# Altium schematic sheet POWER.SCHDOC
size A4; DrawnBy: *Drawb By
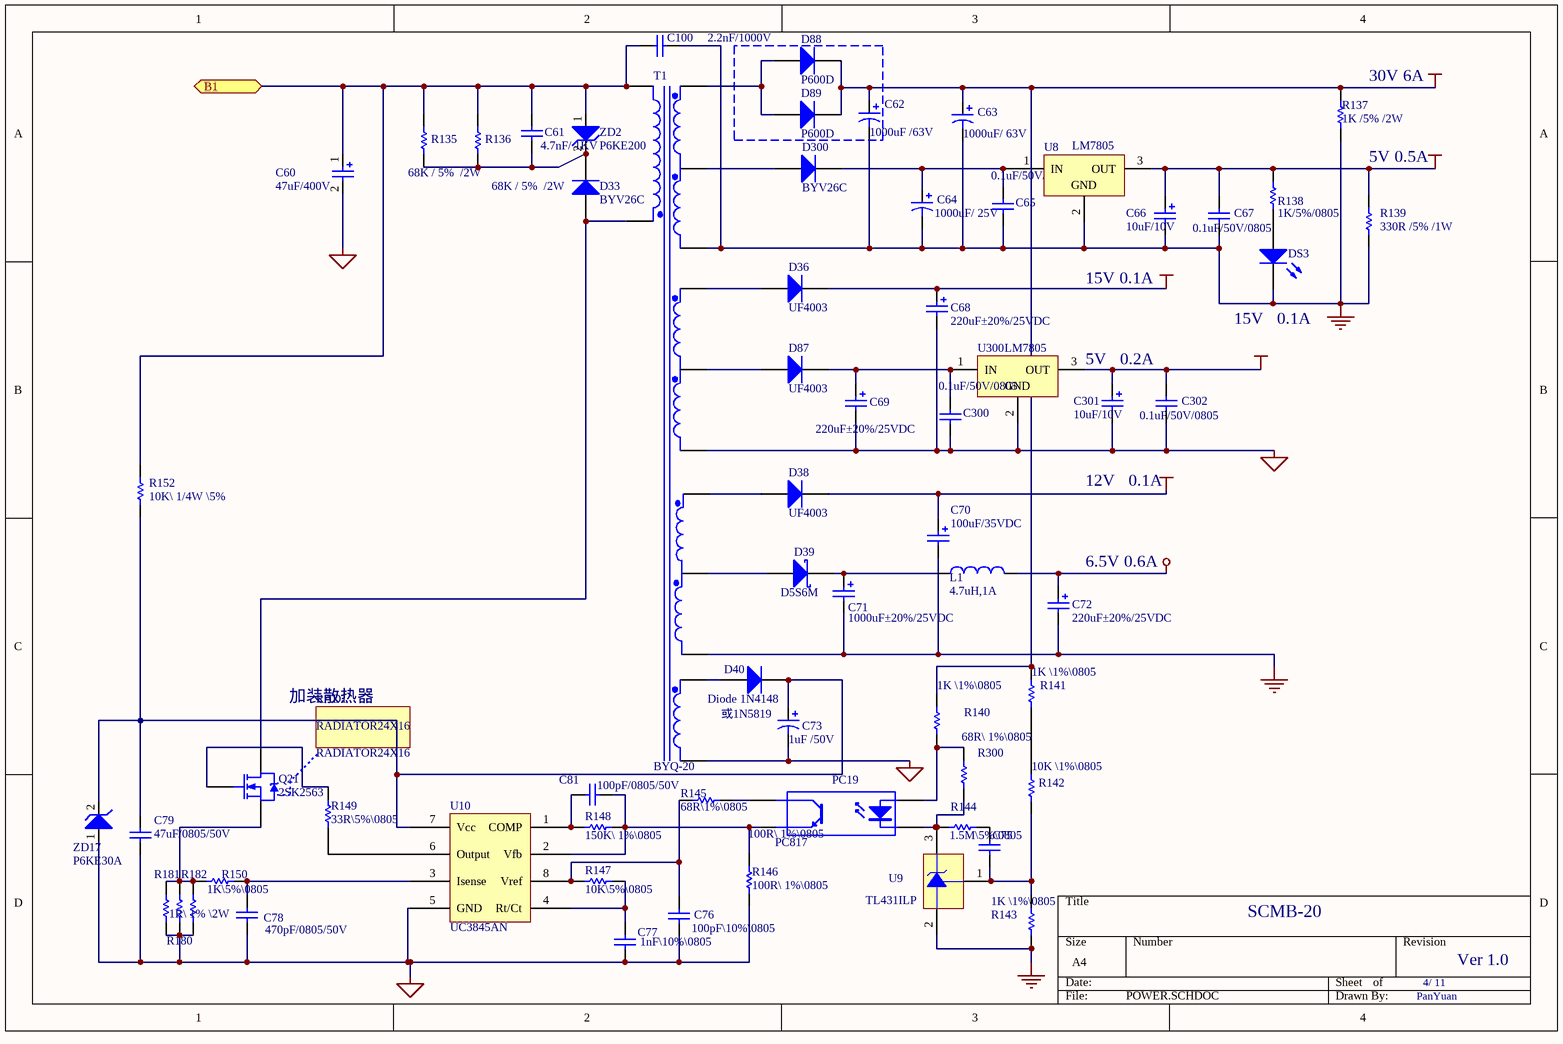
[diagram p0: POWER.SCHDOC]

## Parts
C60  82uF/400V  [CAPP10-22x25]  (value not drawn)
C61  4.7nF/ 1KV  [RAD-0.3]
C62  1000uF /63V  [CAPP7.5-16x25]
C63  1000uF/ 63V  [CAPP7.5-16x25]
C64  1000uF/ 25V  [CAPP5-10x20]
C65  0.1uF/50V/0805  [CC2012-0805]
C66  10uF/10V  [CAPP2-5x11]
C67  0.1uF/50V/0805  [CC2012-0805]
C68  220uF±20%/25VDC  [CAP3.5-8X11.5]
C69  220uF±20%/25VDC  [CAP3.5-8X11.5]
C70  100uF/35VDC  [CAP3.5-8X11.5]
C71  1000uF±20%/25VDC  [CAPP5-10x20]
C72  220uF±20%/25VDC  [CAP3.5-8X11.5]
C73  1uF /50V  [CAPP2-5x11]
C75  300pF\10%\0805  [CC2012-0805]  (value not drawn)
C76  100pF\10%\0805  [CC2012-0805]
C77  1nF\10%\0805  [CC2012-0805]
C78  470pF/0805/50V  [CC2012-0805]
C79  value 47uF/0805/50V  [CC2012-0805]  (hidden comment: 100pF/0805/50V)
C81  value 100pF/0805/50V  [CC2012-0805]  (hidden comment: 100pF/10%/0805)
C100  2.2nF/1000V  [RAD-0.3]
C300  0.1uF/50V/0805  [CC2012-0805]
C301  10uF/10V  [CAPP2-5x11]
C302  0.1uF/50V/0805  [CC2012-0805]
D33  BYV26C  [DIO-6]
D36  UF4003  [DO-14 -- D]
D38  UF4003  [DO-14 -- D]
D39  D5S6M  [D5S6M]
D40  Diode 1N4148  [DIO7.1-3.9x1.9]
D87  UF4003  [DO-14 -- D]
D88  P600D  [P600D]
D89  P600D  [P600D]
D300  BYV26C  [DIO-6]
DS3  LED0  [DIO-2]  (value not drawn)
L1  4.7uH,1A  [Inductor-8.5x10]
PC19  PC817  [DIP-4]
Q21  2SK2563  [TO-220]
R135  68K / 5%  /2W  [R4]
R136  68K / 5%  /2W  [R4]
R137  1K /5% /2W  [R4]
R138  1K/5%/0805  [CR2012-0805]
R139  330R /5% /1W  [R4]
R140  1K \1%\0805  [CR2012-0805]
R141  1K \1%\0805  [CR2012-0805]
R142  10K \1%\0805  [CR2012-0805]
R143  1K \1%\0805  [CR2012-0805]
R144  1.5M\5%\0805  [CR2012-0805]
R145  value 68R\1%\0805  [CR2012-0805]  (hidden comment: Res1)
R146  100R\ 1%\0805  [CR2012-0805]
R147  10K\5%\0805  [CR2012-0805]
R148  150K\ 1%\0805  [CR2012-0805]
R149  33R\5%\0805  [CR2012-0805]
R150  1K\5%\0805  [CR2012-0805]
R152  value 10K\ 1/4W \5%  [CR2012-0805]  (hidden comment: Res1)
R180  1R\ 1% \2W  [CR3225-1210]  (value not drawn)
R181  1R\ 1% \2W  [CR3225-1210]
R182  1R\ 1% \2W  [CR3225-1210]  (value not drawn)
R300  68R\ 1%\0805  [CR2012-0805]
RAD1  RADIATOR24X16  [RADIATOR24X16]
T1  BYQ-20  [BYQ-01]
U8  LM7805  [KC03]
U9  TL431ILP  [BCY-W3/E4]
U10  UC3845AN  [DIP-8]
U300  LM7805  [KC03]
ZD2  P6KE200  [DIO-10]
ZD17  P6KE30A  [DIO-10]

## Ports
B1

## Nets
+5V2: C301.1 C302.2 U300.3(OUT)
+5V3: C66.1 C67.2 R138.2 R139.1 U8.3(OUT)
+6.3V1: C72.1 L1.2
+12V1: C70.1 D38.K
+15V2: C68.1 D36.K
+30V3: C62.1 C63.1 D88.2 D89.2 R137.1 R140.1 R141.2
GND1: C70.2 C71.2 C72.2 T1.8(Sec3-)
GND3: C60.2 C68.2 C69.2 C73.2 C76.1 C77.1 C78.1 C79.1 C300.1 C301.2 C302.1 R146.1 R180.1 R181.1 R182.1 T1.7(Sec3-) T1.16(Sec3+) U10.5(GND) U300.2(GND) ZD17.1(A)
GND4: C62.2 C63.2 C64.2 C65.1 C66.2 C67.1 C100.1 DS3.2(K) R137.2 R139.2 R143.1 T1.15(Sec2-) U8.2(GND) U9.2(A)
B1: C60.1 C61.2 C100.2 R135.1 R136.1 R152.2 T1.1(Pri+) ZD2.1(A) ; port B1
NetC61_1: C61.1 D33.2(K) R135.2 R136.2 ZD2.2(K)
NetC64_1: C64.1 C65.2 D300.2(K) U8.1(IN)
NetC69_1: C69.1 C300.2 D87.K U300.1(IN)
NetC71_1: C71.1 D39.K L1.1
NetC73_1: C73.1 C79.2 D40.2 R152.1 U10.7(Vcc) ZD17.2(K)
NetC75_1: C75.1 R142.1 R143.2 U9.1(REF)
NetC75_2: C75.2 R144.1
NetC76_2: C76.2 R145.2 R147.2 U10.8(Vref)
NetC77_2: C77.2 R147.1 U10.4(Rt/Ct)
NetC78_2: C78.2 R150.1 U10.3(Isense)
NetC81_1: C81.1 R148.1 U10.1(COMP)
NetC81_2: C81.2 PC19.4(E) R146.2 R148.2 U10.2(Vfb)
NetD33_1: D33.1(A) Q21.2(D) T1.5(Pri-)
NetD36_A: D36.A T1.11(Sec3+)
NetD38_A: D38.A T1.10(Sec3+)
NetD39_A: D39.A T1.9(Sec3+)
NetD40_1: D40.1 T1.6(Sec3+)
NetD87_A: D87.A T1.12(Sec3+)
NetD88_1: D88.1 D89.1 T1.13(Sec1+)
NetD300_1: D300.1(A) T1.14(Sec2+)
NetDS3_1: DS3.1(A) R138.1
NetPC19_1: PC19.1(A) R140.2 R300.1
NetPC19_2: PC19.2(K) R144.2 R300.2 U9.3(K)
NetPC19_3: PC19.3(C) R145.1
NetQ21_1: Q21.1(G) R149.2
NetQ21_3: Q21.3(S) R150.2 R180.2 R181.2 R182.2
NetR141_1: R141.1 R142.2
NetR149_1: R149.1 U10.6(Output)

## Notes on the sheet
- (near R137) 30V 6A
- 5V 0.5A
- 15V 0.1A
- 5V   0.2A
- (near DS3) 15V   0.1A
- 12V   0.1A
- (near C72) 6.5V 0.6A
- (near RAD1) 加装散热器
- 或1N5819
- SCMB-20
- 4/ 11
- Ver 1.0
- PanYuan

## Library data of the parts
C60 = Cap3-8.4X20: Polarized Capacitor (Axial)
C61 C75-C79 C81 C100 = Cap: Capacitor
C62 C64 = Cap Pol2: Polarized Capacitor (Axial); Value: 100pF
C63 C73 = Cap Pol2: Polarized Capacitor (Axial)
C65 C67 C300 C302 = CAP_0603: Capacitor
C66 C301 = CAP_T_B_S: Capacitor
C68 C69 C72 = CAP1: 220uF/25V
C70 = CAP1: 47uF/25V
C71 = CAP_T_D_S
D33 D40 D300 = Diode 1N4148: High Conductance Fast Diode
D39 = Diode 11DQ03: Schottky Rectifier; Revision 1: 10-Jul-2000: SIM Model Added.; Revision 2: 17-Jul-2002: Re-released for DXP Platform.; Code - JEDEC: DO-204-AL
D88 D89 = DIOED: Diode
DS3 = LED0: Typical INFRARED GaAs LED
L1 = Inductor: Value: 10mH
PC19 = Optoisolator1: Optoisolator
Q21 = IRFB59N10D: HEXFET Power MOSFET; Package Information: Latest Revision: Feb-1997; Note: Pin 2 is electrically connected to Tab (Drain).
R135-R137 R139 = RES_1210: Resistor
R138 = RES_0805: Resistor
R140-R149 R152 R181 R300 = Res1: Resistor
R150 = Res1: Resistor; Value: 1K\1%\0805
R180 R182 = Res1: Resistor; Value: 0.33R\ 1% \2W
U8 U300 = LM2930-8KC: 3-Terminal Positive Regulator
U9 = TL431ILP: Programmable Precision Reference; PackageDocument: 1996
U10 = UC3842AN
ZD2 ZD17 = DIODE RD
